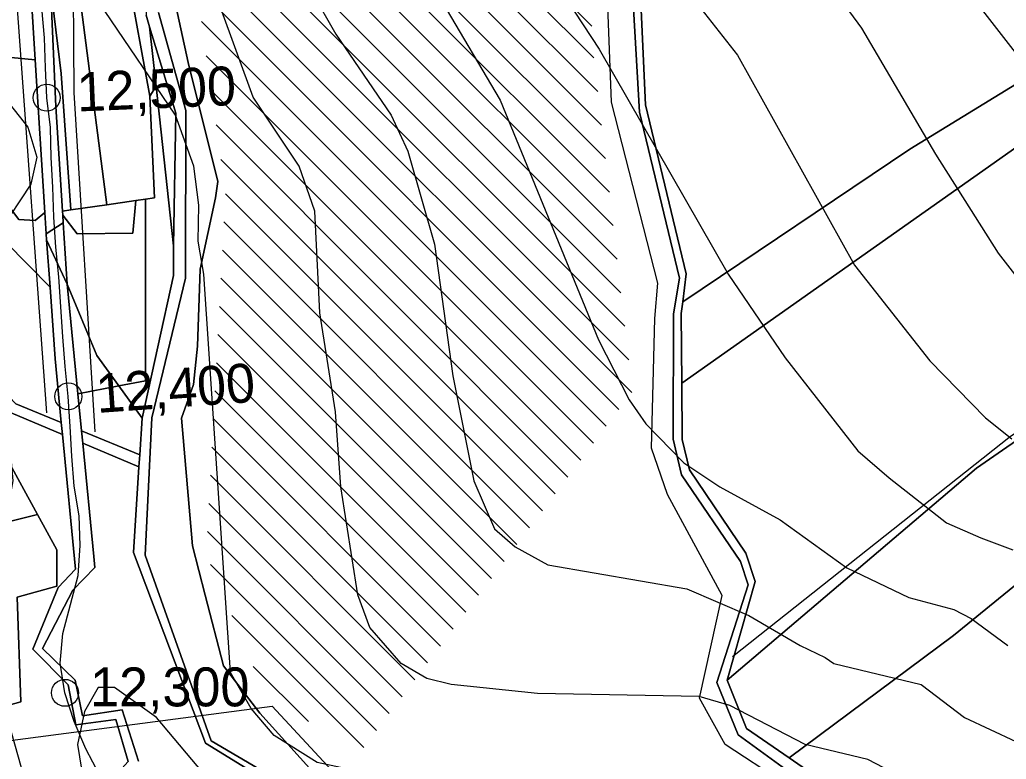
# Model space of a CAD drawing. Extents: x -510989 to -501240, y -1184665 to -1176098.
# Drawn here: x -509892.7 to -509563.3, y -1178778.9 to -1178532.1 of the extents above; entities that cross this region are included whole.
import ezdxf

# ---------------------------------------------------------------- set-up
doc = ezdxf.new("R2010")
doc.units = 0
for name, color, linetype in [('NAVRH_interakcni_prvky', 7, 'Continuous'), ('NAVRH_revitalizace_toku', 7, 'Continuous'), ('orna_puda', 7, 'Continuous'), ('ostatni_plocha_x_neplodna_puda', 7, 'Continuous'), ('ostatni_plocha_x_ostatni_komunikace', 7, 'Continuous'), ('STAV_erozne_ohrozene_plochy', 7, 'Continuous'), ('STAV_systematicke_odvodneni', 7, 'Continuous'), ('trasovani_toku', 7, 'Continuous'), ('trvaly_travni_porost', 7, 'Continuous'), ('vodni_plocha_x_vodni_tok_v_koryte_umelem', 7, 'Continuous'), ('vrstevnice_01', 7, 'Continuous'), ('vrstevnice_02', 7, 'Continuous'), ('zahrada', 7, 'Continuous')]:
    doc.layers.add(name, color=color, linetype=linetype)

msp = doc.modelspace()

# ---------------------------------------------------------------- linework, layer by layer
at = {"layer": 'NAVRH_interakcni_prvky'}
msp.add_lwpolyline([(-509385.29, -1178536.46), (-509406.8, -1178569.3), (-509561.91, -1178671.2), (-509654.75, -1178744.79)], dxfattribs=at)
at = {"layer": 'NAVRH_revitalizace_toku'}
for points in [[(-510060.1, -1177738.31), (-510046.04, -1177776.27), (-510042.52, -1177800.88), (-510055.18, -1177879.61), (-510059.4, -1177948.51), (-510041.82, -1177997.72), (-510013.7, -1178078.56), (-509968.71, -1178171.36), (-509924.51, -1178222.53), (-509906.94, -1178282.99), (-509903.42, -1178334.31), (-509883.74, -1178387.03), (-509875.3, -1178456.63), (-509874.6, -1178556.46), (-509867.57, -1178669.64)], [(-510079.08, -1177742.53), (-510057.99, -1177785.41), (-510068.53, -1177883.83), (-510073.46, -1177950.62), (-510054.47, -1178009.67), (-510024.24, -1178091.92), (-509980.66, -1178181.91), (-509942.44, -1178221.73), (-509934.15, -1178235.7), (-509920.62, -1178289.39), (-509918.19, -1178331.5), (-509899.91, -1178389.14), (-509890.77, -1178450.3), (-509893.58, -1178526.93), (-509883.74, -1178663.31)]]:
    msp.add_lwpolyline(points, dxfattribs=at)
at = {"layer": 'orna_puda'}
for points in [[(-509689.32, -1178501.37), (-509685.8, -1178562.93), (-509672.39, -1178618.33), (-509674.47, -1178630.32), (-509674.5, -1178672.14), (-509671.73, -1178683.97), (-509652.1, -1178712.92), (-509649.5, -1178720.7), (-509659.95, -1178753.29), (-509652.84, -1178770.83), (-509632.06, -1178785.91)], [(-509792.83, -1178785.4), (-509812.54, -1178763.59), (-509824.65, -1178747.77), (-509830.74, -1178724.2), (-509835, -1178707.71), (-509838.69, -1178665.11), (-509834.62, -1178653.85), (-509833.29, -1178641.04), (-509832.37, -1178615.34), (-509827.25, -1178591.52), (-509826.58, -1178586.15), (-509836.43, -1178546.39), (-509841.29, -1178523.86)]]:
    msp.add_lwpolyline(points, dxfattribs=at)
for points in [[(-509865.37, -1178516.48), (-509851.42, -1178511.71), (-509850.5, -1178530.66), (-509849.32, -1178534.55), (-509847.15, -1178554.28), (-509849.24, -1178557.64), (-509856.72, -1178516.82), (-509873.23, -1178519.17)], [(-509873.23, -1178519.17), (-509856.72, -1178516.82), (-509849.24, -1178557.64), (-509847.66, -1178591.58), (-509850.71, -1178592.02), (-509853.85, -1178592.47), (-509863.53, -1178593.86)], [(-509898.45, -1178523.77), (-509903.72, -1178530.21), (-509907.1, -1178543.67), (-509887.47, -1178545.47), (-509884.25, -1178596.44), (-509887.51, -1178599.15), (-509892.95, -1178598.8), (-509930.09, -1178549.48), (-509933.25, -1178541.43), (-509933.54, -1178531.63), (-509910.21, -1178525.15)], [(-509847.15, -1178554.28), (-509841.3, -1178607.54), (-509841.3, -1178617.49), (-509851.81, -1178665.08), (-509859.62, -1178654.31), (-509850.71, -1178652.59), (-509850.71, -1178592.02), (-509847.66, -1178591.58), (-509849.24, -1178557.64)], [(-509850.71, -1178592.02), (-509850.71, -1178652.59), (-509859.62, -1178654.31), (-509866.97, -1178644.18), (-509876.84, -1178620.4), (-509878.15, -1178599.87), (-509878.31, -1178597.37), (-509873.45, -1178603.61), (-509854.91, -1178603.33), (-509853.85, -1178592.47)], [(-509876.84, -1178620.4), (-509866.97, -1178644.18), (-509859.62, -1178654.31), (-509873.26, -1178656.93)], [(-509859.62, -1178654.31), (-509851.81, -1178665.08), (-509852.6, -1178677.38), (-509872.04, -1178669.34), (-509873.26, -1178656.93)], [(-509911.22, -1178703.41), (-509886.71, -1178697.22), (-509880.24, -1178709.03), (-509880.31, -1178719.92), (-509880.32, -1178721.13), (-509893.56, -1178724.82), (-509892.3, -1178759.71), (-509902.41, -1178762.58), (-509915.08, -1178704.38)]]:
    msp.add_lwpolyline(points, close=True, dxfattribs=at)
at = {"layer": 'ostatni_plocha_x_neplodna_puda'}
for points in [[(-509882.43, -1178520.77), (-509873.23, -1178519.17), (-509863.53, -1178593.86), (-509875.65, -1178595.6), (-509878.87, -1178550.11)], [(-509878.87, -1178550.11), (-509875.65, -1178595.6), (-509878.4, -1178595.99), (-509880.63, -1178561.06), (-509882.43, -1178520.77)], [(-509892.72, -1178523.77), (-509888.85, -1178523.77), (-509887.47, -1178545.47), (-509907.1, -1178543.67), (-509903.72, -1178530.21), (-509898.45, -1178523.77)], [(-509528.28, -1178534.13), (-509523.84, -1178541.35), (-509519.72, -1178548.07), (-509541.69, -1178561.72), (-509671.68, -1178653.37), (-509671.85, -1178630.12), (-509671.35, -1178626.27), (-509595.55, -1178575.29)], [(-509912.23, -1178591.4), (-509882.54, -1178621.37), (-509880.83, -1178645.35), (-509878.78, -1178666.56), (-509893.96, -1178660.28), (-509906.93, -1178646.77), (-509910.72, -1178637.13)], [(-509853.85, -1178592.47), (-509854.91, -1178603.33), (-509873.45, -1178603.61), (-509878.31, -1178597.37), (-509878.4, -1178595.99), (-509875.65, -1178595.6), (-509863.53, -1178593.86)]]:
    msp.add_lwpolyline(points, close=True, dxfattribs=at)
for points in [[(-509841.29, -1178523.86), (-509836.43, -1178546.39), (-509826.58, -1178586.15), (-509827.25, -1178591.52), (-509832.37, -1178615.34), (-509833.29, -1178641.04), (-509834.62, -1178653.85), (-509838.69, -1178665.11), (-509835, -1178707.71), (-509830.74, -1178724.2), (-509824.65, -1178747.77), (-509812.54, -1178763.59), (-509792.83, -1178785.4)], [(-509780.43, -1178801.13), (-509828.76, -1178772.81), (-509850.78, -1178710.85), (-509848.55, -1178664.98), (-509837.36, -1178618.43), (-509837.18, -1178562.42), (-509846.29, -1178529.7)], [(-509895.56, -1178663.36), (-509878.39, -1178670.57), (-509874.05, -1178715.54), (-509879.81, -1178721.59), (-509888.23, -1178742.24), (-509876.47, -1178754.07), (-509873.96, -1178767.48), (-509860.56, -1178765.61), (-509856.51, -1178779.64), (-509865.55, -1178789.78), (-509860.34, -1178800.65), (-509841.3, -1178828.61), (-509840.61, -1178829.62), (-509832.32, -1178836.33), (-509823.05, -1178842.11), (-509816.77, -1178843.87), (-509822.64, -1178848.68), (-509826.02, -1178847.74), (-509849.16, -1178841.27), (-509878.08, -1178796.21), (-509887.97, -1178801.8), (-509897.79, -1178785.97)], [(-509853.04, -1178779.57), (-509858.43, -1178762.42), (-509871.72, -1178764.47), (-509874.19, -1178752.51), (-509885.08, -1178742.01), (-509874.89, -1178722.52), (-509867.56, -1178714.98), (-509867.93, -1178711.25), (-509871.64, -1178673.4), (-509852.85, -1178681.29), (-509854.71, -1178709.95), (-509830.59, -1178773.6), (-509804.89, -1178789.32)], [(-509902.41, -1178762.58), (-509892.3, -1178759.71), (-509893.56, -1178724.82), (-509880.32, -1178721.13), (-509880.31, -1178719.92), (-509880.24, -1178709.03), (-509886.71, -1178697.22), (-509899.19, -1178674.41)]]:
    msp.add_lwpolyline(points, dxfattribs=at)
at = {"layer": 'ostatni_plocha_x_ostatni_komunikace'}
for points in [[(-509632.06, -1178785.91), (-509652.84, -1178770.83), (-509659.95, -1178753.29), (-509649.5, -1178720.7), (-509652.1, -1178712.92), (-509671.73, -1178683.97), (-509674.5, -1178672.14), (-509674.47, -1178630.32), (-509672.39, -1178618.33), (-509685.8, -1178562.93), (-509689.32, -1178501.37)], [(-509686.43, -1178501.79), (-509683.78, -1178560.52), (-509670.15, -1178616.94), (-509671.35, -1178626.27), (-509671.85, -1178630.12), (-509671.68, -1178653.37), (-509671.55, -1178672.19), (-509669.03, -1178682.37), (-509650.24, -1178710.17), (-509647.13, -1178719.66), (-509656.51, -1178752.52), (-509650.05, -1178768.62), (-509635.85, -1178778.43), (-509628.57, -1178783.46)], [(-509933.54, -1178531.63), (-509933.25, -1178541.43), (-509930.09, -1178549.48), (-509914.58, -1178589.02), (-509912.23, -1178591.4), (-509910.72, -1178637.13), (-509906.93, -1178646.77), (-509893.96, -1178660.28), (-509878.78, -1178666.56), (-509878.39, -1178670.57), (-509895.56, -1178663.36), (-509910.68, -1178647.6), (-509916.32, -1178636.1), (-509915.02, -1178620.87), (-509917.14, -1178610.5), (-509917.63, -1178587.83), (-509935.86, -1178541.31), (-509935.86, -1178531.7)], [(-509846.29, -1178529.7), (-509837.18, -1178562.42), (-509837.36, -1178618.43), (-509848.55, -1178664.98), (-509850.78, -1178710.85), (-509828.76, -1178772.81), (-509780.43, -1178801.13), (-509775.25, -1178807.45), (-509804.89, -1178789.32), (-509830.59, -1178773.6), (-509854.71, -1178709.95), (-509852.85, -1178681.29), (-509852.6, -1178677.38), (-509851.81, -1178665.08), (-509841.3, -1178617.49), (-509841.3, -1178607.54), (-509840.6, -1178563.26), (-509849.32, -1178534.55), (-509850.5, -1178530.66)]]:
    msp.add_lwpolyline(points, dxfattribs=at)
for points in [[(-509847.15, -1178554.28), (-509849.32, -1178534.55), (-509840.6, -1178563.26), (-509841.3, -1178607.54)], [(-509872.04, -1178669.34), (-509852.6, -1178677.38), (-509852.85, -1178681.29), (-509871.64, -1178673.4)]]:
    msp.add_lwpolyline(points, close=True, dxfattribs=at)
at = {"layer": 'STAV_erozne_ohrozene_plochy'}
for p, q in [((-509832.5, -1178403.49), (-509701.73, -1178534.27)), ((-509831.37, -1178414.53), (-509701.01, -1178544.88)), ((-509830.24, -1178425.56), (-509699.72, -1178556.07)), ((-509829.1, -1178436.59), (-509698.42, -1178567.27)), ((-509827.97, -1178447.63), (-509697.13, -1178578.46)), ((-509826.83, -1178458.66), (-509695.83, -1178589.66)), ((-509826.99, -1178468.4), (-509694.54, -1178600.85)), ((-509827.99, -1178477.3), (-509693.24, -1178612.05)), ((-509828.98, -1178486.21), (-509691.95, -1178623.24)), ((-509829.98, -1178495.11), (-509690.65, -1178634.44)), ((-509830.98, -1178504.01), (-509689.36, -1178645.63)), ((-509831.97, -1178512.92), (-509688.35, -1178656.54)), ((-509832.97, -1178521.82), (-509692.61, -1178662.18)), ((-509832, -1178532.68), (-509696.87, -1178667.82)), ((-509830.38, -1178544.21), (-509701.13, -1178673.46)), ((-509828.75, -1178555.74), (-509705.39, -1178679.1)), ((-509827.12, -1178567.26), (-509709.65, -1178684.74)), ((-509825.5, -1178578.79), (-509713.91, -1178690.38)), ((-509824.01, -1178590.18), (-509718.17, -1178696.02)), ((-509824.51, -1178599.58), (-509722.43, -1178701.66)), ((-509825.01, -1178608.98), (-509726.69, -1178707.3)), ((-509825.51, -1178618.38), (-509730.95, -1178712.94)), ((-509826.01, -1178627.78), (-509735.21, -1178718.58)), ((-509826.51, -1178637.18), (-509739.46, -1178724.22)), ((-509827.01, -1178646.58), (-509743.72, -1178729.86)), ((-509827.51, -1178655.97), (-509747.98, -1178735.5)), ((-509828.01, -1178665.37), (-509752.24, -1178741.14)), ((-509828.51, -1178674.77), (-509756.5, -1178746.78)), ((-509829.01, -1178684.17), (-509760.76, -1178752.42)), ((-509829.51, -1178693.57), (-509765.02, -1178758.06)), ((-509830.01, -1178702.97), (-509769.28, -1178763.7)), ((-509828.97, -1178713.91), (-509773.54, -1178769.34)), ((-509821.82, -1178730.96), (-509777.8, -1178774.98)), ((-509814.68, -1178748), (-509796.31, -1178766.37))]:
    msp.add_line(p, q, dxfattribs=at)
at = {"layer": 'STAV_systematicke_odvodneni'}
for p, q in [((-509695.1, -1178559.6), (-509697.23, -1178505.06)), ((-509679.59, -1178620.03), (-509695.1, -1178559.6)), ((-509680.66, -1178631.79), (-509679.59, -1178620.03)), ((-509681.73, -1178675.11), (-509680.66, -1178631.79)), ((-509676.39, -1178690.62), (-509681.73, -1178675.11)), ((-509658.21, -1178724.31), (-509676.39, -1178690.62)), ((-509665.7, -1178758.53), (-509658.21, -1178724.31)), ((-509657.14, -1178774.04), (-509665.7, -1178758.53)), ((-509902.49, -1178773.5), (-509808.41, -1178761.2)), ((-509808.41, -1178761.2), (-509787.03, -1178784.2)), ((-509635.76, -1178787.94), (-509657.14, -1178774.04))]:
    msp.add_line(p, q, dxfattribs=at)
at = {"layer": 'trasovani_toku'}
for p, q in [((-509884.35, -1178538.16), (-509885.24, -1178528.2)), ((-509884.09, -1178548.16), (-509884.35, -1178538.16)), ((-509883.64, -1178558.15), (-509884.09, -1178548.16)), ((-509882.39, -1178568.07), (-509883.64, -1178558.15)), ((-509882.21, -1178578.07), (-509882.39, -1178568.07)), ((-509881.64, -1178588.05), (-509882.21, -1178578.07)), ((-509881.23, -1178598.04), (-509881.64, -1178588.05)), ((-509880.58, -1178608.02), (-509881.23, -1178598.04)), ((-509879.56, -1178617.97), (-509880.58, -1178608.02)), ((-509878.9, -1178627.95), (-509879.56, -1178617.97)), ((-509878.22, -1178637.93), (-509878.9, -1178627.95)), ((-509877.48, -1178647.9), (-509878.22, -1178637.93)), ((-509876.44, -1178657.84), (-509877.48, -1178647.9)), ((-509875.86, -1178667.83), (-509876.44, -1178657.84)), ((-509875.23, -1178677.81), (-509875.86, -1178667.83)), ((-509874.45, -1178687.78), (-509875.23, -1178677.81)), ((-509872.81, -1178697.64), (-509874.45, -1178687.78)), ((-509872.44, -1178707.63), (-509872.81, -1178697.64)), ((-509873.13, -1178717.61), (-509872.44, -1178707.63)), ((-509875.68, -1178727.28), (-509873.13, -1178717.61)), ((-509878.25, -1178736.95), (-509875.68, -1178727.28)), ((-509879.21, -1178746.9), (-509878.25, -1178736.95)), ((-509877.56, -1178756.76), (-509879.21, -1178746.9)), ((-509874.5, -1178766.28), (-509877.56, -1178756.76)), ((-509870.61, -1178775.49), (-509874.5, -1178766.28)), ((-509865.9, -1178784.32), (-509870.61, -1178775.49))]:
    msp.add_line(p, q, dxfattribs=at)
for centre in [(-509883.64, -1178558.15), (-509876.44, -1178657.84), (-509877.56, -1178756.76)]:
    msp.add_circle(centre, 4.5, dxfattribs=at)
at = {"layer": 'trvaly_travni_porost'}
for points in [[(-509528.28, -1178534.13), (-509595.55, -1178575.29), (-509671.35, -1178626.27), (-509670.15, -1178616.94), (-509683.78, -1178560.52), (-509686.43, -1178501.79), (-509678.34, -1178467.64), (-509668.58, -1178416.23), (-509656.4, -1178379.19), (-509652.79, -1178368.21), (-509594.35, -1178332.56), (-509586.19, -1178337.22), (-509579.9, -1178343.14), (-509557.86, -1178330.84)], [(-509562.14, -1178932.28), (-509566.44, -1178924.06), (-509569.79, -1178915.5), (-509576.71, -1178897.88), (-509584.84, -1178883.94), (-509605.41, -1178859.83), (-509608.22, -1178841.97), (-509618.72, -1178802.31), (-509628.57, -1178783.46), (-509635.85, -1178778.43), (-509580.92, -1178737.68), (-509547.35, -1178710.26)]]:
    msp.add_lwpolyline(points, dxfattribs=at)
for points in [[(-509373.8, -1178463.87), (-509364.87, -1178458.71), (-509374.14, -1178485.74), (-509394.14, -1178589.57), (-509418.11, -1178608.34), (-509474.6, -1178653.53), (-509547.35, -1178710.26), (-509580.92, -1178737.68), (-509635.85, -1178778.43), (-509650.05, -1178768.62), (-509656.51, -1178752.52), (-509573.26, -1178681.79), (-509468.88, -1178609.54), (-509404.06, -1178569.52), (-509394.47, -1178559), (-509386, -1178541.39), (-509387.47, -1178513.19), (-509384.73, -1178493.38), (-509378.53, -1178479)], [(-509373.8, -1178463.87), (-509378.53, -1178479), (-509384.73, -1178493.38), (-509387.47, -1178513.19), (-509386, -1178541.39), (-509394.47, -1178559), (-509404.06, -1178569.52), (-509468.88, -1178609.54), (-509573.26, -1178681.79), (-509656.51, -1178752.52), (-509647.13, -1178719.66), (-509650.24, -1178710.17), (-509669.03, -1178682.37), (-509671.55, -1178672.19), (-509671.68, -1178653.37), (-509541.69, -1178561.72), (-509519.72, -1178548.07)], [(-509930.09, -1178549.48), (-509892.95, -1178598.8), (-509887.51, -1178599.15), (-509884.25, -1178596.44), (-509883.8, -1178603.54), (-509883.67, -1178605.55), (-509882.54, -1178621.37), (-509912.23, -1178591.4), (-509914.58, -1178589.02)]]:
    msp.add_lwpolyline(points, close=True, dxfattribs=at)
at = {"layer": 'vodni_plocha_x_vodni_tok_v_koryte_umelem'}
for points in [[(-509882.43, -1178520.77), (-509880.63, -1178561.06), (-509878.4, -1178595.99), (-509878.31, -1178597.37), (-509878.15, -1178599.87), (-509883.8, -1178603.54), (-509884.25, -1178596.44), (-509887.47, -1178545.47), (-509888.85, -1178523.77)], [(-509856.51, -1178779.64), (-509860.56, -1178765.61), (-509873.96, -1178767.48), (-509876.47, -1178754.07), (-509888.23, -1178742.24), (-509879.81, -1178721.59), (-509874.05, -1178715.54), (-509878.39, -1178670.57), (-509878.78, -1178666.56), (-509880.83, -1178645.35), (-509882.54, -1178621.37), (-509883.67, -1178605.55), (-509876.84, -1178620.4), (-509873.26, -1178656.93), (-509872.04, -1178669.34), (-509871.64, -1178673.4), (-509867.93, -1178711.25), (-509867.56, -1178714.98), (-509874.89, -1178722.52), (-509885.08, -1178742.01), (-509874.19, -1178752.51), (-509871.72, -1178764.47), (-509858.43, -1178762.42), (-509853.04, -1178779.57)]]:
    msp.add_lwpolyline(points, dxfattribs=at)
msp.add_lwpolyline([(-509878.15, -1178599.87), (-509876.84, -1178620.4), (-509883.67, -1178605.55), (-509883.8, -1178603.54)], close=True, dxfattribs=at)
at = {"layer": 'vrstevnice_01'}
for points in [[(-509862.41, -1178214), (-509839.81, -1178237), (-509817.5, -1178247), (-509816.19, -1178255), (-509817.59, -1178270), (-509815.09, -1178301), (-509814.31, -1178321), (-509796.91, -1178424), (-509786.81, -1178459), (-509771.19, -1178493), (-509732.31, -1178559), (-509699.41, -1178639), (-509689.19, -1178659), (-509683.69, -1178667), (-509671, -1178680), (-509659, -1178688), (-509638.81, -1178699), (-509616.59, -1178715), (-509595.81, -1178725), (-509580.81, -1178729), (-509575, -1178732), (-509562.81, -1178741)], [(-509719.31, -1178439), (-509709.09, -1178463), (-509692.19, -1178494), (-509653, -1178544), (-509614, -1178614), (-509588.81, -1178646), (-509570.31, -1178665), (-509561.5, -1178672)], [(-509557.5, -1178813), (-509573, -1178798), (-509609.5, -1178779), (-509630.5, -1178774), (-509655.59, -1178761), (-509665.81, -1178758), (-509719.81, -1178757), (-509748.59, -1178754), (-509756.81, -1178752), (-509765.31, -1178747), (-509775.81, -1178735), (-509779.81, -1178724), (-509785.41, -1178688), (-509787.19, -1178663), (-509792.5, -1178630), (-509794.19, -1178596), (-509799.41, -1178581), (-509814.69, -1178558), (-509825.69, -1178528)], [(-509572.09, -1178528), (-509526.19, -1178587)], [(-509551.5, -1178889), (-509588.91, -1178862), (-509603.69, -1178854), (-509635.91, -1178841), (-509685.91, -1178824), (-509709.91, -1178820), (-509752.31, -1178818), (-509787.31, -1178811), (-509800.19, -1178807), (-509815.5, -1178799), (-509829.31, -1178786), (-509847, -1178765), (-509861, -1178755), (-509866.5, -1178755), (-509871, -1178763), (-509873.41, -1178774)], [(-509873.41, -1178774), (-509869.19, -1178800), (-509862, -1178818), (-509856, -1178828), (-509844.31, -1178842), (-509835.19, -1178850), (-509819.91, -1178859), (-509805.91, -1178866), (-509794.19, -1178876), (-509787, -1178889), (-509780.91, -1178891), (-509765.5, -1178889), (-509744.09, -1178892), (-509725.31, -1178899), (-509710.69, -1178907), (-509698.91, -1178916)]]:
    msp.add_lwpolyline(points, dxfattribs=at)
at = {"layer": 'vrstevnice_02'}
for points in [[(-509536.41, -1178648), (-509565.91, -1178610), (-509586.81, -1178577), (-509611.59, -1178535), (-509663.59, -1178464)], [(-509720.81, -1178509), (-509699.19, -1178542), (-509656.19, -1178617), (-509637.19, -1178645), (-509612.91, -1178676), (-509602.41, -1178685), (-509583.31, -1178700), (-509571.81, -1178705), (-509561.09, -1178709)], [(-509795.09, -1178523), (-509787.09, -1178537), (-509768.69, -1178564), (-509763.09, -1178576), (-509754.19, -1178607), (-509748.09, -1178651), (-509741.09, -1178686), (-509734.19, -1178702), (-509727.31, -1178708), (-509716.41, -1178714), (-509669.91, -1178722), (-509649.31, -1178731), (-509632.09, -1178741), (-509623.81, -1178745), (-509620.91, -1178747), (-509591.69, -1178754), (-509577.31, -1178765), (-509560.09, -1178773)], [(-509840.69, -1178564), (-509864.31, -1178529)], [(-509901.31, -1178530), (-509906.19, -1178540), (-509906.69, -1178547), (-509890, -1178568), (-509886.91, -1178578), (-509888.91, -1178587), (-509899.59, -1178603), (-509904.69, -1178624), (-509903.59, -1178635), (-509897.41, -1178658), (-509894.91, -1178686), (-509900.69, -1178717), (-509902.5, -1178719), (-509898.81, -1178758), (-509886.69, -1178801), (-509876.59, -1178824), (-509859.59, -1178849), (-509843.41, -1178863), (-509819.91, -1178879), (-509808.91, -1178889), (-509801.69, -1178902), (-509798.59, -1178913), (-509792.5, -1178922)], [(-509562.41, -1178849), (-509579.41, -1178831), (-509592.19, -1178822), (-509611.19, -1178811), (-509626.41, -1178805), (-509646.31, -1178801), (-509705.5, -1178791), (-509760.69, -1178787), (-509793.41, -1178780), (-509807.69, -1178771), (-509815.41, -1178762), (-509822.31, -1178750), (-509831.19, -1178617), (-509833.09, -1178606), (-509832.91, -1178594), (-509834.5, -1178581), (-509840.69, -1178564)]]:
    msp.add_lwpolyline(points, dxfattribs=at)
at = {"layer": 'zahrada'}
msp.add_lwpolyline([(-509899.19, -1178674.41), (-509886.71, -1178697.22), (-509911.22, -1178703.41), (-509909.05, -1178676.36)], close=True, dxfattribs=at)

# ---------------------------------------------------------------- texts
at = {"layer": 'trasovani_toku'}
for s, rotation, p in [('12,500', 2.3771, (-509873.36, -1178562.77)), ('12,400', 4.0394, (-509866.76, -1178663.37))]:
    msp.add_text(s, height=13, rotation=rotation, dxfattribs=at).set_placement(p)
msp.add_text('12,300', height=13, dxfattribs=at).set_placement((-509869.16, -1178761.28))

doc.saveas('drawing.dxf')
